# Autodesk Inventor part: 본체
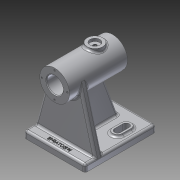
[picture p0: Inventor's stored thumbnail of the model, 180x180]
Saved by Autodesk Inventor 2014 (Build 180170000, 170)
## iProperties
Created: 2019-10
Part Number: 본체
Material: Aluminum 6061
Document SubType Name: Modeling
Designer: kh
Density: 2.71 g/cm^3
Appearance: Aluminum - Flat
Mass: 588.619 g
Surface Area: 540.35 cm^2
Volume: 217.202 cm^3
Author: kh
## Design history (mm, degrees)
sketch "Sketch1"
  geometry: L1 (-41, 21)-(41, 21); L2 (41, 21)-(41, 0); L3 (41, 0)-(-41, 0); L4 (-41, 0)-(-41, 21); 2 further points
  constraints: 8 end point, 2 parallel, 1 coincident, 1 horizontal, 1 midpoint, 1 perpendicular
  dimensions: "d0" = 42 diameter of L1 L3; "d1" = 82 distance of L1.start L1.end
revolve "Revolution1" sketch "Sketch1" stored, may be unused: angle "d2" = 90 deg
sketch "Sketch2"
  geometry: L1 (41, -21)-(41, 21) reference; L2 (-41, -21)-(-41, 21) reference; L3 (-41, 0)-(21, 0); L4 (21, 0)-(21, 14.5); L5 (21, 14.5)-(-41, 14.5); L6 (-41, 14.5)-(-41, 0); L7 (21, 0)-(41, 0); L8 (41, 0)-(41, 11.5); L9 (41, 11.5)-(21, 11.5); L10 (21, 11.5)-(21, 0); 1 further point
  constraints: 16 end point, 4 parallel, 2 horizontal, 2 perpendicular, 1 midpoint, 1 point on line
  dimensions: "d3" = 29 diameter of L5 L3; "d4" = 23 diameter of L9 L7; "d5" = 62 distance of L4.end L5.end
revolve "Revolution2" sketch "Sketch2" stored, may be unused: angle "d6" = 90 deg
chamfer "Chamfer1" distance "d7" = 1; stored, may be unused: second distance "d8" = 2, angle "d9" = 45 deg
workplane "Work Plane1"
sketch "Sketch3"
  geometry: L1 (41, 21)-(41, -21) reference; C1 r 11 at (16, 0); 1 further point
  constraints: 1 centre point, 1 horizontal alignment
  dimensions: "d11" = 22 diameter of C1; "d12" = 25 distance from line of C1.centre L1
extrude "Extrusion1" join sketch "Sketch3" stored distance "d13" = 10; taper "d14" = 0 deg
hole "Hole1" diameter "d17" = 4.917; stored, may be unused: countersink angle "d21" = 90 deg, drill point angle "d23" = 0 deg; dims "d18" = 6, "d19" = 14, "d20" = 4, "d22" = 8, "d87" = 10, "d88" = 10
fillet "Fillet1" dims "d24" = 3
workplane "Work Plane2"
sketch "Sketch4"
  geometry: L1 (-41, 21)-(-41, -21) reference; L2 (-41, 43)-(59, 43); L3 (59, 43)-(59, -43); L4 (59, -43)-(-41, -43); L5 (-41, -43)-(-41, 43); L6 (0, 0)-(-41, 0)
  constraints: 10 end point, 2 parallel, 2 perpendicular, 1 horizontal, 1 midpoint, 1 point on line, 1 other
  dimensions: "d26" = 100 distance of L3.end L4.end; "d27" = 86 distance of L2.end L3.end
extrude "Extrusion2" join sketch "Sketch4" distance "d28" = 10; taper "d29" = 0 deg
fillet "Fillet2" dims "d38" = 3
fillet "Fillet3" dims "d39" = 3
sketch "Sketch7"
  geometry: 1 further point
workplane "Work Plane4"
  workplane "Work Plane3"
sketch "Sketch8"
  geometry: L1 (-40, -76)-(40, -76) reference; L2 (-42.896, -78.217)-(-20.272, 5.48); L3 (20.272, 5.48)-(42.896, -78.217); A1 r 21 centre (0, 0) between (-20.298, 5.385) and (20.298, 5.385) reference; A2 r 3 centre (40, -79) between (43, -79) and (40, -76) reference; A3 r 3 centre (-40, -79) between (-40, -76) and (-43, -79) reference; 3 further points
  constraints: 8 point on circle, 4 end point, 4 tangent
extrude "Extrusion4" join sketch "Sketch8" distance "d40" = 10; taper "d41" = 0 deg
sketch "Sketch9"
  geometry: L1 (31.598, -16.592)-(31.598, 16.592); L2 (31.598, 16.592)-(36.402, 16.592); L3 (36.402, 16.592)-(36.402, -16.592); L4 (36.402, -16.592)-(31.598, -16.592); L5 (31.598, -16.592)-(36.402, 16.592); L6 (-56, -43)-(38, -43) reference; L7 (41, -40)-(41, 40) reference; 2 further points
  constraints: 2 end point, 1 midpoint, 2 other
  dimensions: "d46" = 43 distance from line of point (34, 0) L6; "d47" = 7 distance from line of point (34, 0) L7
emboss "Emboss1" sketch "Sketch9" dims "d0" = 42, "d1" = 82, "d48" = 0.5, "d49" = 0
sketch "Sketch10" dims "d50" = 36
  geometry: C1 r 21 at (0, 0) reference; 3 further points
  constraints: 2 vertical alignment, 1 coincident, 2 other
hole "Hole2" sketch "Sketch10" at (0, 18) diameter "d51" = 2.459; stored, may be unused: countersink angle "d55" = 82 deg, drill point angle "d57" = 118 deg; dims "d52" = 8, "d53" = 3.023, "d54" = 4, "d56" = 10
pattern_circular "Circular Pattern1" dims angle "d59" = 360 deg
mirror "Mirror1"
sketch "Sketch11"
  geometry: L1 (-56, -76)-(38, -76) reference; L2 (-41, -21)-(41, -21) reference; L3 (-44, -76)-(-23.982, -21); L4 (-59, -86)-(-59, -79) reference; 2 further points
  constraints: 2 end point, 2 point on line
  dimensions: "d63" = 15 distance from line of L3.start L4; "d64" = 70 deg angle of L1 L3
feature "Rib1" sketch "Sketch11" dims "d65" = 1, "d66" = 10, "d67" = 0, "d68" = 0, "d69" = 1, "d70" = 1
fillet "Fillet11" dims "d72" = 3
fillet "Fillet12" dims "d73" = 3
sketch "Sketch12"
  geometry: L1 (-33, -27)-(-21, -27); L2 (-33, -31.5)-(-21, -31.5); L3 (-21, -22.5)-(-33, -22.5); L4 (-59, 40)-(-59, -40) reference; L5 (-21, -20)-(-33, -20); L6 (-33, -34)-(-21, -34); A1 r 4.5 centre (-33, -27) between (-33, -22.5) and (-33, -31.5); A2 r 4.5 centre (-21, -27) between (-21, -31.5) and (-21, -22.5); A3 r 7 centre (-33, -27) between (-33, -20) and (-33, -34); A4 r 7 centre (-21, -27) between (-21, -34) and (-21, -20); 2 further points
  constraints: 12 end point, 8 point on circle, 4 centre point, 4 tangent, 2 parallel, 1 horizontal, 1 midpoint, 3 other
  dimensions: "d75" = 12 distance of L1.end L1.start; "d77" = 9 distance between parallel lines of L2 L3; "d78" = 26 distance from line of L1.start L4; "d79" = 27 horizontal distance of point (0, 0) point (-27, -27); "d80" = 14 distance between parallel lines of L6 L5
extrude "Extrusion5" join sketch "Sketch12" distance "d81" = 3; taper "d82" = 0 deg
sketch "Sketch13"
  geometry: L1 (-33, -27)-(-21, -27); L2 (-33, -31.5)-(-21, -31.5); L3 (-21, -22.5)-(-33, -22.5); A1 r 7 centre (-21, -27) between (-21, -34) and (-21, -20) reference; A2 r 7 centre (-33, -27) between (-33, -20) and (-33, -34) reference; A3 r 4.5 centre (-33, -27) between (-33, -22.5) and (-33, -31.5); A4 r 4.5 centre (-21, -27) between (-21, -31.5) and (-21, -22.5); 2 further points
  constraints: 8 end point, 4 point on circle, 4 tangent, 2 centre point, 1 horizontal, 1 midpoint, 1 parallel
  dimensions: "d83" = 9 diameter of A4
extrude "Extrusion6" cut sketch "Sketch13" stored distance "d84" = 3; taper "d85" = 0 deg
fillet "Fillet13" dims "d86" = 3
mirror "Mirror2"
body "Solid1"
node "Projected Loop1"
other parameters: "d10" = 24, "d25" = -86, "d35" = -15
